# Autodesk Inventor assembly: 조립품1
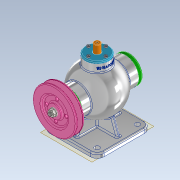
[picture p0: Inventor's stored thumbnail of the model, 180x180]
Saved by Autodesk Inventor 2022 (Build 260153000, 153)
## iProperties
Created: 2024-04
Part Number: 조립품1
Document SubType Name: Assembly
Designer: Admin
Author: Admin
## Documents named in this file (16)
- C:\Users\Admin\Desktop\740406V1012\조립품1.iam
- C:\Users\Admin\Desktop\740406V1012\부품1.ipt
- C:\Users\Admin\Desktop\740406V1012\뒤커버.ipt
- C:\Users\Admin\Desktop\740406V1012\앞커버.ipt
- C:\Users\Admin\Desktop\740406V1012\상부커버.ipt
- C:\Users\Admin\Desktop\740406V1012\베어링- 6202.ipt
- KS B 2023 - 6202 - 15 x 35 x 11 - 7.8.ipt
- C:\Users\Admin\Desktop\740406V1012\칼라.ipt
- C:\Users\Admin\Desktop\740406V1012\편심축.ipt
- C:\Users\Admin\Desktop\740406V1012\키 4 x 4 x 12.ipt
- C:\Users\Admin\Desktop\740406V1012\오일실 15 30 7.ipt
- C:\Users\Admin\Desktop\740406V1012\V-벨트풀리.ipt
- C:\Users\Admin\Desktop\740406V1012\너트 M8.ipt
- C:\Users\Admin\Desktop\740406V1012\볼트 M4 x 16.ipt
- C:\Users\Admin\Desktop\740406V1012\슬라이드.ipt
- C:\Users\Admin\Desktop\740406V1012\볼트 M4 x 12.ipt
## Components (15 placed, 4 different names)
1. KS B 2023 - 6202 - 15 x 35 x 11 - 7.8:1
2. KS B 2023 - 6202 - 15 x 35 x 11 - 7.8:2
3. V-벨트풀리:1
4. ISO 4762 M4 x 16:1
5. ISO 4762 M4 x 16:2
6. ISO 4762 M4 x 16:3
7. ISO 4762 M4 x 16:4
8. ISO 4762 M4 x 16:5
9. ISO 4762 M4 x 16:6
10. ISO 4762 M4 x 16:7
11. ISO 4762 M4 x 16:8
12. KS B 1021 - 에 따름 ISO 1207 - 미터 A  M 4 x 12:1
13. KS B 1021 - 에 따름 ISO 1207 - 미터 A  M 4 x 12:2
14. KS B 1021 - 에 따름 ISO 1207 - 미터 A  M 4 x 12:3
15. KS B 1021 - 에 따름 ISO 1207 - 미터 A  M 4 x 12:4
